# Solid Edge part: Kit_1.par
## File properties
Author: bmolnar
Last saved by: bmolnar
Revision: 78
Sűrűség: 0,000 kg/m^3
Pontosság: 0,990
Username: bmolnar
Dokumentum tartalom típus: 0
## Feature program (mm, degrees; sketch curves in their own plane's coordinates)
base feature "unnamed BaseFeature 1"
sketch for "unnamed Hole 1" plane through (-44.5, 44.5, 16.5) normal (0, 0, 1) x-axis (1, 0, 0)
  hole centre (0, 0) bore radius 4.188
hole "unnamed Hole 1" through
sketch for "unnamed Hole 2" plane through (-44.5, 44.5, 16.5) normal (0, 0, 1) x-axis (1, 0, 0)
  hole centre (89, 0) bore radius 4.188
hole "unnamed Hole 2" through
sketch for "unnamed Hole 3" plane through (-44.5, 44.5, 16.5) normal (0, 0, 1) x-axis (1, 0, 0)
  hole centre (89, -89) bore radius 4.188
hole "unnamed Hole 3" through
sketch for "unnamed Hole 4" plane through (-44.5, 44.5, 16.5) normal (0, 0, 1) x-axis (1, 0, 0)
  hole centre (0, -89) bore radius 4.188
hole "unnamed Hole 4" through
pattern "unnamed Pattern 1" of "unnamed Hole 1", "unnamed Hole 2", "unnamed Hole 3", "unnamed Hole 4"
sketch for "Furat_9" plane through (56.65, 0, 56.65) normal (-1, 0, 0) x-axis (0, -1, 0)
  hole centre (0, -47.65) bore radius 4.283
hole "Furat_9" nominal diameter 9.728 finite  ThreadDepth = 12 mm
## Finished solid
Body 1: solid body, 293 faces, 720 edges, 444 vertices.
  Faces by surface: plane 143, cylinder 70, swept 56, cone 15, torus 8, spline 1
  Edges by curve: line 430, circle 140, spline 120, ellipse 28, curve on surface 2
Bounding box of the edges (mm; curved faces can reach further): 113.300 x 113.300 x 19.500, from (-56.65, -56.65, 0) to (56.65, 56.65, 19.5).
Cylindrical faces by radius (mm): R0.2 x48, R0.2006 x2, R0.2007 x2, R4.188 x4, R4.283 x1, R6 x1, R6.35 x4, R6.55 x4, R6.75 x4
Conical faces (half-angle, radius in mm at the cone's reference point): 0.5 deg R12.25 x4, 0.5 deg R35 x2, 45 deg R4.185 x4, 45 deg R4.985 x4, 45 deg R6.25 x1
Toroidal faces (ring radius, tube radius in mm): R6.05 r0.3 x2, R6.15 r0.2 x6
Planar faces by outward normal: +x 17, +y 16, +z 18, -x 14, -y 14, -z 1, oblique 63
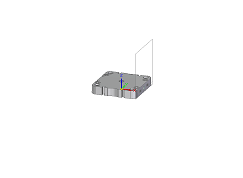
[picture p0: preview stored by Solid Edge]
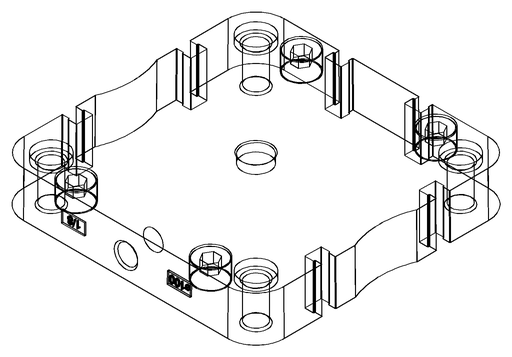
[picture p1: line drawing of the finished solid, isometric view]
